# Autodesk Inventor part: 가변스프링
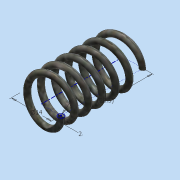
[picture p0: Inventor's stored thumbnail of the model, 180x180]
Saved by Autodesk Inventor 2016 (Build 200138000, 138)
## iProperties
Created: 2020-02
Part Number: 가변스프링
Material: 강철
Document SubType Name: Modeling
Designer: Administrator
Density: 7.85 g/cm^3
Appearance: 플레이트
Mass: 6.4407 g
Surface Area: 16.6485 cm^2
Volume: 0.820472 cm^3
Author: Administrator
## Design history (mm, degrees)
sketch "스케치1"
  geometry: L1 (0, 0)-(7, 0); L2 (7, 0)-(7, 35.5); L3 (7, 35.5)-(0, 35.5); L4 (0, 35.5)-(0, 0); C1 r 1 at (7, 0)
  constraints: 8 end point, 2 parallel, 1 centre point, 1 coincident, 1 horizontal, 1 perpendicular
  dimensions: "d0" = 14 diameter of L2 L4; "d1" = 35.5 distance between parallel lines of L1 L3 (derived); "d2" = 2 diameter of C1
feature "코일1" pitch "d3" = 10; turns "d5" = 6; dims "d4" = 35.5 (= d1), "d6" = 0, angle "d7" = 90 deg, angle "d8" = 90 deg, "d9" = 0, "d10" = 0
sketch "스케치3"
  geometry: L1 (-8, 0)-(-6, 0) reference; 1 further point
  constraints: 1 horizontal alignment
extrude "돌출2" cut sketch "스케치3" distance "d13" = 10; taper "d14" = 0 deg
node "작업 평면1"
sketch "스케치4"
  geometry: L1 (1, 0)-(-1, 0) reference; 1 further point
  constraints: 1 horizontal alignment
extrude "돌출3" cut sketch "스케치4" distance "d16" = 10; taper "d17" = 0 deg
node "솔리드1"
node "절단 모서리 투영2"
node "절단 모서리 투영3"
other parameters: "d15" = 90 deg
